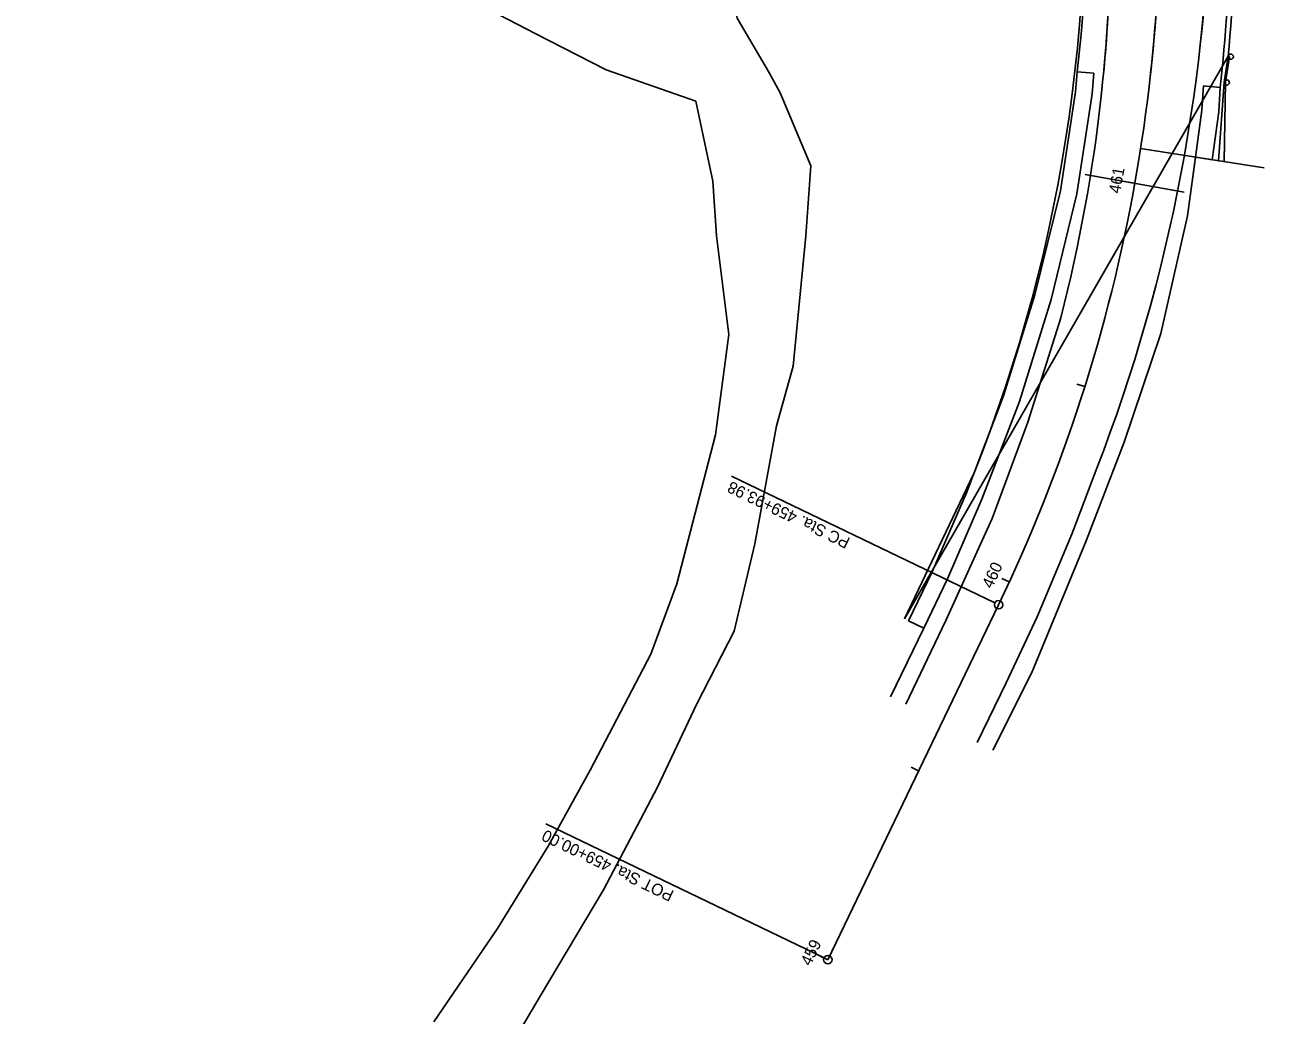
# Model space of a CAD drawing. Extents: x 2355002 to 2355569, y 708374 to 709566.
# Drawn here: x 2355092.3 to 2355388.2, y 708948.1 to 709184.4 of the extents above; entities that cross this region are included whole.
import ezdxf

# ---------------------------------------------------------------- set-up
doc = ezdxf.new("R2010")
doc.units = 0
for name, color, linetype in [('BD_X_Building', 7, 'Continuous'), ('HY_X_Water_Edge', 7, 'Continuous'), ('PM_X_CL_Double_Solid', 7, 'Continuous'), ('PM_X_Edge_Line', 7, 'Continuous'), ('PV_X_EOP', 7, 'Continuous'), ('RD_X_GR_Lt', 7, 'Continuous'), ('RD_X_GR_Rt', 7, 'Continuous'), ('RD_X_Wall', 7, 'Continuous'), ('SH_Text', 7, 'Continuous'), ('UT_X_Water_Cells', 7, 'Continuous')]:
    doc.layers.add(name, color=color, linetype=linetype)

msp = doc.modelspace()

# ---------------------------------------------------------------- linework, layer by layer
at = {"layer": 'BD_X_Building'}
for p, q in [((2355379.57, 709176.9), (2355302.32, 709042.68)), ((2355388.17, 709150.26), (2355358.67, 709154.88)), ((2355345.47, 709148.7), (2355369.09, 709144.48))]:
    msp.add_line(p, q, dxfattribs=at)
at = {"layer": 'HY_X_Water_Edge'}
for points in [[(2355252.5, 709166.15), (2355231.06, 709173.66), (2355214.15, 709182.36), (2355203.37, 709187.9), (2355192.59, 709193.45), (2355183.53, 709205.69), (2355174.46, 709217.93), (2355164.58, 709222.52), (2355164.39, 709236.17), (2355153.02, 709259.61), (2355143.04, 709280.19), (2355127.94, 709298.41), (2355115.77, 709313.1), (2355105.23, 709336.59), (2355094.69, 709360.09), (2355095.83, 709378.33), (2355096.98, 709396.58), (2355097.73, 709408.64), (2355093.09, 709413.75), (2355102.05, 709442.02), (2355092.33, 709458.07)], [(2355264.27, 709216.73), (2355261.27, 709208.52), (2355259.9, 709196.1), (2355262.4, 709185.96), (2355269.83, 709173.27), (2355272.6, 709168.16), (2355279.97, 709150.79), (2355278.74, 709134.04), (2355275.76, 709102.96), (2355271.72, 709088.75), (2355266.58, 709060.54), (2355261.65, 709039.76), (2355252.67, 709022.22), (2355243.38, 709002.5), (2355230.45, 708978), (2355215.36, 708952.6), (2355198.96, 708924.88)], [(2355189.96, 708946.52), (2355205.17, 708968.81), (2355217.22, 708988.41), (2355227.26, 709006.56), (2355241.74, 709034.22), (2355247.94, 709051), (2355257.22, 709086.56), (2355260.39, 709110.48), (2355257.47, 709134.08), (2355256.57, 709147.09), (2355252.5, 709166.15)]]:
    msp.add_lwpolyline(points, dxfattribs=at)
at = {"layer": 'PM_X_CL_Double_Solid'}
msp.add_line((2355284.01, 708961.34), (2355324.76, 709046.03), dxfattribs=at)
for start in [334.3, 353.532]:
    msp.add_arc((2354973.05, 709215.29), 390.32, start, 5.4609, dxfattribs=at)
at = {"layer": 'PM_X_Edge_Line'}
for points in [[(2355339.61, 709114.5), (2355331.76, 709089.58), (2355323.2, 709066.63), (2355312.21, 709042.29), (2355302.66, 709022.32)], [(2355348.23, 709078.63), (2355342.26, 709062.89), (2355333.96, 709043.16), (2355326.57, 709027.4), (2355319.66, 709013.13)]]:
    msp.add_lwpolyline(points, dxfattribs=at)
for centre, radius, start, end in [((2354973.64, 709223.69), 401.69, 338.83, 359.6749), ((2354972.82, 709208.78), 378.71, 345.5839, 1.8559)]:
    msp.add_arc(centre, radius, start, end, dxfattribs=at)
at = {"layer": 'PV_X_EOP'}
for p, q in [((2355347.51, 709172.83), (2355343.53, 709173.16)), ((2355373.66, 709169.88), (2355377.64, 709169.43))]:
    msp.add_line(p, q, dxfattribs=at)
for points in [[(2355347.51, 709172.83), (2355347.11, 709167.94), (2355343.48, 709144.04), (2355337.29, 709118.88), (2355329.72, 709094.53), (2355320.78, 709071.24), (2355312.54, 709052.23), (2355306.89, 709040.48)], [(2355373.66, 709169.88), (2355373.31, 709164.03), (2355371.77, 709152.83)]]:
    msp.add_lwpolyline(points, dxfattribs=at)
for centre, radius, start, end in [((2354857.73, 709226.22), 523, 353.7662, 1.7538), ((2354973.64, 709223.69), 401.69, 352.3321, 359.6749), ((2355066.64, 709207.56), 279.01, 352.9182, 2.7522), ((2354972.82, 709208.78), 378.71, 354.5146, 1.8559)]:
    msp.add_arc(centre, radius, start, end, dxfattribs=at)
at = {"layer": 'RD_X_GR_Lt'}
for p, q in [((2355379.57, 709176.9), (2355378.61, 709170.72)), ((2355379.89, 709176.85), (2355379.57, 709176.9)), ((2355379.89, 709176.85), (2355379.57, 709176.9)), ((2355378.94, 709170.68), (2355379.89, 709176.85)), ((2355378.61, 709170.72), (2355377.24, 709151.97)), ((2355378.64, 709151.77), (2355378.94, 709170.68)), ((2355377.24, 709151.97), (2355378.64, 709151.77))]:
    msp.add_line(p, q, dxfattribs=at)
for centre in [(2355380.18, 709176.8), (2355379.23, 709170.65)]:
    msp.add_circle(centre, 0.625, dxfattribs=at)
msp.add_arc((2354973.05, 709215.29), 408.32, 354.6047, 5.4609, dxfattribs=at)
at = {"layer": 'RD_X_GR_Rt'}
msp.add_line((2355318.8, 709077.15), (2355302.32, 709042.68), dxfattribs=at)
msp.add_arc((2354973.05, 709215.29), 372.32, 338.2199, 5.4609, dxfattribs=at)
at = {"layer": 'RD_X_Wall'}
for p, q in [((2355357.28, 709146.59), (2355355.31, 709146.94)), ((2355345.36, 709098.07), (2355343.45, 709098.67)), ((2355327.33, 709051.47), (2355325.51, 709052.31)), ((2355284.01, 708961.34), (2355324.76, 709046.03)), ((2355305.69, 709006.39), (2355303.89, 709007.26)), ((2355284.01, 708961.34), (2355282.2, 708962.21))]:
    msp.add_line(p, q, dxfattribs=at)
for centre in [(2355324.76, 709046.03), (2355284.01, 708961.34)]:
    msp.add_circle(centre, 1, dxfattribs=at)
msp.add_arc((2354973.05, 709215.29), 390.32, 334.3, 5.4609, dxfattribs=at)
at = {"layer": 'SH_Text'}
for p, q in [((2355323.86, 709046.46), (2355261.01, 709076.71)), ((2355283.1, 708961.77), (2355216.66, 708993.75))]:
    msp.add_line(p, q, dxfattribs=at)
at = {"layer": 'UT_X_Water_Cells'}
for p, q in [((2355375.72, 709152.21), (2355371.77, 709152.83)), ((2355303.28, 709042.21), (2355306.89, 709040.48)), ((2355306.89, 709040.48), (2355299, 709024.07))]:
    msp.add_line(p, q, dxfattribs=at)
for points in [[(2355343.53, 709173.16), (2355343.13, 709168.41), (2355339.55, 709144.82), (2355333.43, 709119.96), (2355325.94, 709095.85), (2355317.07, 709072.75), (2355308.9, 709053.9), (2355303.28, 709042.21)], [(2355377.64, 709169.43), (2355377.3, 709163.63), (2355375.72, 709152.21)], [(2355371.77, 709152.83), (2355369.83, 709138.83), (2355363.46, 709110.73), (2355354.73, 709084.84), (2355345.67, 709061.24), (2355332.68, 709029.85), (2355323.4, 709011.31)]]:
    msp.add_lwpolyline(points, dxfattribs=at)

# ---------------------------------------------------------------- texts
at = {"layer": 'BD_X_Building'}
msp.add_text('X', height=0.14, rotation=25.0808, dxfattribs=at).set_placement((2355376.43, 709152.01))
at = {"layer": 'RD_X_Wall'}
for s, rotation, p in [('461', 79.8622, (2355353.77, 709144.02)), ('460', 65.183, (2355323.2, 709049.69)), ('459', 64.3, (2355279.86, 708959.65))]:
    msp.add_text(s, height=2.8, rotation=rotation, dxfattribs=at).set_placement(p)
at = {"layer": 'SH_Text'}
for s, p in [('PC Sta. 459+93.98', (2355289.55, 709061.83)), ('POT Sta. 459+00.00', (2355247.49, 708977.62))]:
    msp.add_text(s, height=2.8, rotation=154.3, dxfattribs=at).set_placement(p)

doc.saveas('drawing.dxf')
